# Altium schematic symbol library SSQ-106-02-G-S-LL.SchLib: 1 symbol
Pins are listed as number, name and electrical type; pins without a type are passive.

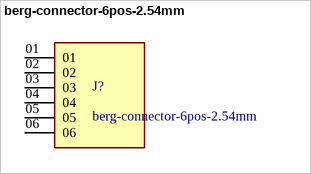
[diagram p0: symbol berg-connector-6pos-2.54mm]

## berg-connector-6pos-2.54mm
designator J?
MF: Samtec; MP: SSQ-106-02-G-S-LL
footprint SAMTEC_SSQ-106-02-G-S-LL
pins: 01, 02, 03, 04, 05, 06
